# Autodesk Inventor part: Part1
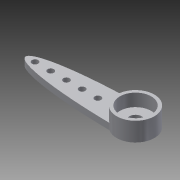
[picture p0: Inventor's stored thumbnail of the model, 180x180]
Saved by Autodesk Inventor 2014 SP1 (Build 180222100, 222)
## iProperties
Created: 2017-05
Part Number: Part1
Material: PVC-Piping
Document SubType Name: Modeling
Designer: L.Đ.P
Density: 1.4 g/cm^3
Appearance: Smooth - White
Author: L.Đ.P
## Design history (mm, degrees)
sketch "Sketch1" dims "d0" = 17.5
  geometry: L1 (0, 0)-(0, -2.5); L2 (0, 0)-(0, 2.5); 1 further point; 1 other entity
  constraints: 4 end point, 2 vertical, 1 coincident, 4 other
  dimensions: "d1" = 2.5 distance of L1.start L1.end
extrude "Extrusion1" new body sketch "Sketch1" stored distance "d2" = 1; taper "d3" = 0 deg
sketch "Sketch2"
  geometry: C1 r 3 at (0, 0); 1 further point; 1 other entity
  constraints: 1 centre point, 1 coincident, 1 other
  dimensions: "d4" = 6 diameter of C1
extrude "Extrusion2" join sketch "Sketch2" distance "d5" = 2; taper "d6" = 0 deg; dims "d23" = 1, "d24" = 0
sketch "Sketch3"
  geometry: C1 r 3 at (0, 0) reference; C2 r 2.5 at (0, 0)
  constraints: 1 centre point, 1 coincident
  dimensions: "d7" = 5 diameter of C2
extrude "Extrusion3" cut sketch "Sketch3" distance "d8" = 2; taper "d9" = 0 deg
sketch "Sketch4"
  geometry: C1 r 2 at (0, 0); 1 further point; 1 other entity
  constraints: 1 centre point, 1 coincident, 1 other
  dimensions: "d10" = 4 diameter of C1
extrude "Extrusion4" cut sketch "Sketch4" distance "d11" = 0.5; taper "d12" = 0 deg
sketch "Sketch5"
  geometry: C1 r 2 at (0, 0) reference; C2 r 1 at (0, 0)
  constraints: 1 centre point, 1 coincident
  dimensions: "d13" = 2 diameter of C2
extrude "Extrusion5" cut sketch "Sketch5" stored distance "d14" = 1; taper "d15" = 0 deg
sketch "Sketch6"
  geometry: L1 (0, 0)-(0, 1.269); L2 (0, 0)-(1.481, 0); C1 r 0.5 at (16, 0); 1 other entity
  constraints: 4 end point, 1 centre point, 1 perpendicular, 1 point on line, 1 vertical, 1 other
  dimensions: "d16" = 1 diameter of C1; "d17" = 16 distance of L1.start C1.centre
extrude "Extrusion6" cut sketch "Sketch6" stored distance "d18" = 1; taper "d19" = 0 deg
pattern_linear "Rectangular Pattern1" dims "d22" = 2.5
body "Solid1"
